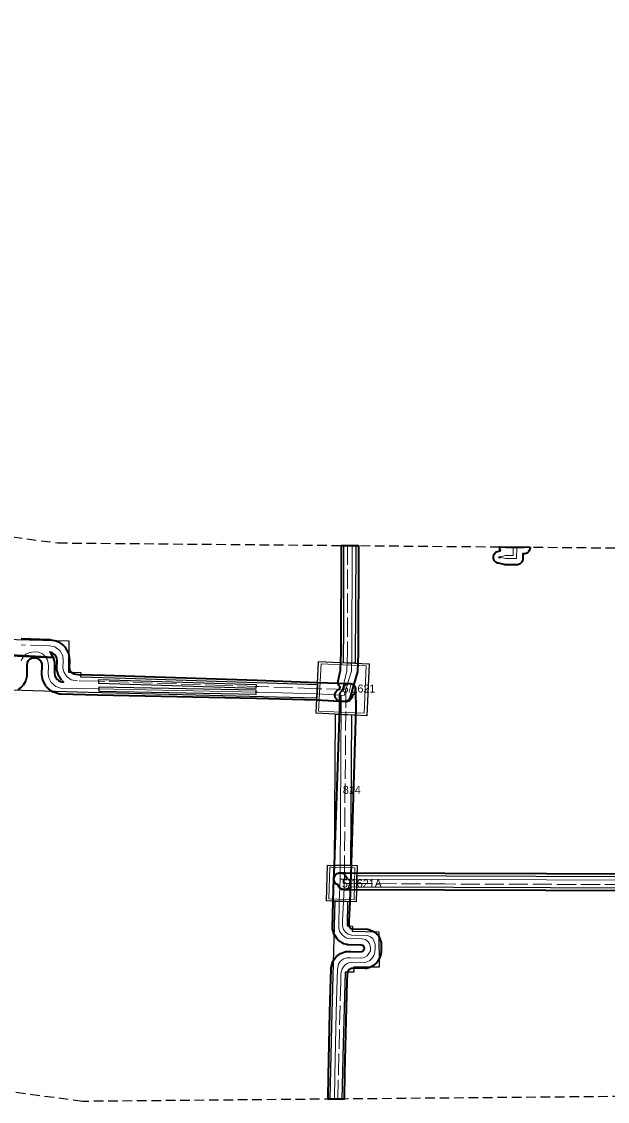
# Model space of a CAD drawing. Extents: x -451331 to -449998, y -1101254 to -1101132.
# Drawn here: x -450463.8 to -450397.9, y -1101253.5 to -1101132.1 of the extents above; entities that cross this region are included whole.
import ezdxf

# ---------------------------------------------------------------- set-up
doc = ezdxf.new("R2010")
doc.units = 0
doc.header["$LTSCALE"] = 0.36
doc.header["$PDMODE"] = 32
doc.header["$PDSIZE"] = 0.18
doc.linetypes.add('LONG_DASHED', pattern=[7.5, 6, -1.5])
doc.linetypes.add('MEDIUM_DASHED', pattern=[4.5, 3, -1.5])
for name, color, linetype, lineweight in [('2', 7, 'Continuous', 13), ('3', 7, 'Continuous', 25), ('62', 7, 'MEDIUM_DASHED', 25), ('8', 7, 'Continuous', 35)]:
    doc.layers.add(name, color=color, linetype=linetype, lineweight=lineweight)
doc.layers.add('4', color=7, linetype='Continuous')

msp = doc.modelspace()

# ---------------------------------------------------------------- linework, layer by layer
at = {"layer": '2'}
for p, q in [((-450409.321, -1101191.258), (-450409.64, -1101191.165)), ((-450427.843, -1101208.474), (-450427.84, -1101207.848)), ((-450427.95, -1101228.513), (-450427.989, -1101229.466))]:
    msp.add_line(p, q, dxfattribs=at)
at = {"layer": '2', "linetype": 'LONG_DASHED'}
for p, q in [((-450427.321, -1101208.495), (-450427.32, -1101207.206)), ((-450427.515, -1101229.486), (-450427.495, -1101229.013))]:
    msp.add_line(p, q, dxfattribs=at)
for points in [[(-450427.111, -1101191.007), (-450427.14, -1101203.013), (-450427.199, -1101205.113), (-450427.493, -1101206.369)], [(-450410.013, -1101192.327), (-450409.396, -1101192.12), (-450408.694, -1101192.129), (-450408.492, -1101192.12), (-450408.499, -1101191.175)], [(-450455.129, -1101206.277), (-450457.469, -1101206.21), (-450458.165, -1101206.097), (-450458.682, -1101205.745), (-450458.981, -1101205.301), (-450459.109, -1101204.789), (-450459.067, -1101203.978), (-450459.126, -1101203.422), (-450459.458, -1101202.817), (-450460.023, -1101202.407), (-450460.6, -1101202.279), (-450463.815, -1101202.179)], [(-450437.08, -1101206.868), (-450437.31, -1101206.859), (-450440.958, -1101206.74), (-450454.5, -1101206.295), (-450455.129, -1101206.277)], [(-450427.493, -1101206.369), (-450427.5, -1101206.398), (-450427.685, -1101207.195)], [(-450427.32, -1101207.206), (-450430.563, -1101207.105), (-450437.08, -1101206.868)], [(-450427.495, -1101229.013), (-450427.475, -1101228.025), (-450427.321, -1101209.263), (-450427.321, -1101208.495)], [(-450428.21, -1101253.252), (-450428.145, -1101250.298), (-450427.888, -1101240.012), (-450427.864, -1101239.152), (-450427.818, -1101238.86), (-450427.715, -1101238.592), (-450427.58, -1101238.376), (-450427.385, -1101238.168), (-450427.162, -1101238.01), (-450426.898, -1101237.894), (-450426.708, -1101237.847), (-450425.142, -1101237.88), (-450424.935, -1101237.831), (-450424.613, -1101237.657), (-450424.36, -1101237.42), (-450424.164, -1101237.106), (-450424.057, -1101236.742), (-450424.033, -1101236.247), (-450424.029, -1101235.836), (-450424.118, -1101235.523), (-450424.294, -1101235.208), (-450424.552, -1101235.01), (-450424.888, -1101234.865), (-450426.684, -1101234.814), (-450427.064, -1101234.693), (-450427.341, -1101234.495), (-450427.576, -1101234.182), (-450427.696, -1101233.808), (-450427.685, -1101233.225), (-450427.579, -1101231.023), (-450427.515, -1101229.486)], [(-450426.579, -1101229.016), (-450427.323, -1101229.013), (-450427.495, -1101229.013)], [(-450393.344, -1101229.141), (-450416.205, -1101229.066), (-450426.579, -1101229.016)]]:
    msp.add_lwpolyline(points, dxfattribs=at)
at = {"layer": '2'}
for points in [[(-450427.094, -1101206.466), (-450427.075, -1101206.4), (-450426.69, -1101205.134), (-450426.623, -1101203.118), (-450426.597, -1101191.011)], [(-450408.113, -1101191.179), (-450408.12, -1101192.486), (-450409.365, -1101192.475), (-450410.013, -1101192.327)], [(-450409.321, -1101191.258), (-450407.313, -1101191.258), (-450407.312, -1101191.186)], [(-450455.194, -1101207.118), (-450457.391, -1101207.074), (-450459.366, -1101207.034), (-450459.921, -1101206.849), (-450460.445, -1101206.396), (-450460.703, -1101205.888), (-450460.774, -1101205.415), (-450460.739, -1101204.626), (-450460.749, -1101204.21), (-450460.872, -1101203.817), (-450461.054, -1101203.524), (-450461.419, -1101203.197), (-450461.831, -1101203.015), (-450462.34, -1101202.969), (-450462.849, -1101203.036), (-450463.273, -1101203.243), (-450463.585, -1101203.55), (-450463.786, -1101203.928)], [(-450427.84, -1101207.848), (-450427.489, -1101207.861), (-450427.094, -1101206.466)], [(-450437.173, -1101207.506), (-450437.33, -1101207.501), (-450440.843, -1101207.426), (-450455.194, -1101207.118)], [(-450427.84, -1101207.848), (-450430.595, -1101207.703), (-450437.173, -1101207.506)], [(-450427.95, -1101228.513), (-450427.942, -1101227.997), (-450427.843, -1101208.474)], [(-450427.989, -1101229.466), (-450428.05, -1101231.01), (-450428.112, -1101234.044), (-450427.993, -1101234.43), (-450427.705, -1101234.838), (-450427.326, -1101235.108), (-450427.004, -1101235.204), (-450425.479, -1101235.241), (-450425.158, -1101235.32), (-450424.872, -1101235.501), (-450424.657, -1101235.765), (-450424.526, -1101236.16), (-450424.553, -1101236.577), (-450424.714, -1101236.89), (-450424.9, -1101237.134), (-450425.315, -1101237.357), (-450425.704, -1101237.398), (-450426.774, -1101237.362), (-450427.193, -1101237.36), (-450427.572, -1101237.493), (-450427.936, -1101237.781), (-450428.143, -1101238.098), (-450428.265, -1101238.648), (-450428.33, -1101240.954), (-450428.404, -1101243.537), (-450428.545, -1101250.606), (-450428.587, -1101253.256)], [(-450427.95, -1101228.513), (-450427.32, -1101228.513), (-450426.595, -1101228.516)], [(-450426.595, -1101228.516), (-450416.203, -1101228.566), (-450393.342, -1101228.641)]]:
    msp.add_lwpolyline(points, dxfattribs=at)
at = {"layer": '3'}
for points in [[(-450427.586, -1101204.181), (-450427.533, -1101200.035), (-450427.522, -1101191.003), (-450426.207, -1101191.015), (-450426.261, -1101204.241)], [(-450430.389, -1101204.049), (-450424.674, -1101204.319), (-450424.95, -1101210.147), (-450430.665, -1101209.877)], [(-450455.059, -1101206.081), (-450437.406, -1101206.62), (-450437.42, -1101207.068), (-450455.073, -1101206.528)], [(-450455.027, -1101206.906), (-450437.424, -1101207.248), (-450437.435, -1101207.773), (-450455.038, -1101207.432)], [(-450428.486, -1101209.98), (-450426.685, -1101210.065), (-450426.803, -1101226.978), (-450428.598, -1101226.947)], [(-450426.141, -1101231.063), (-450429.488, -1101230.97), (-450429.375, -1101226.934), (-450426.049, -1101226.991)], [(-450428.507, -1101230.997), (-450427.131, -1101231.036), (-450427.158, -1101233.762), (-450426.576, -1101233.795), (-450426.583, -1101234.366), (-450423.586, -1101234.43), (-450423.566, -1101238.432), (-450426.442, -1101238.437), (-450426.421, -1101238.977), (-450427.377, -1101238.966), (-450427.614, -1101247.044), (-450427.757, -1101253.248), (-450429.083, -1101253.26), (-450428.882, -1101244.969), (-450428.527, -1101230.997)]]:
    msp.add_lwpolyline(points, close=True, dxfattribs=at)
for points in [[(-450465.786, -1101201.536), (-450458.428, -1101201.743), (-450458.465, -1101205.262), (-450457.108, -1101205.299), (-450457.121, -1101205.769), (-450452.083, -1101205.924), (-450430.512, -1101206.65), (-450430.584, -1101208.162), (-450456.247, -1101207.547), (-450467.469, -1101207.201)], [(-450329.864, -1101232.315), (-450333.399, -1101232.315), (-450333.397, -1101230.456), (-450333.898, -1101230.453), (-450333.898, -1101229.798), (-450359.843, -1101229.58), (-450388.544, -1101229.543), (-450388.534, -1101230.025), (-450389.144, -1101230.033), (-450389.169, -1101232.065), (-450392.677, -1101232.065), (-450392.736, -1101230.012), (-450393.421, -1101230.011), (-450393.431, -1101229.541), (-450426.085, -1101229.419), (-450426.062, -1101228.119), (-450395.865, -1101228.233), (-450345.044, -1101228.383), (-450323.284, -1101228.506)]]:
    msp.add_lwpolyline(points, dxfattribs=at)
at = {"layer": '3', "lineweight": 13}
for points in [[(-450429.341, -1101204.364), (-450425.019, -1101204.553), (-450425.25, -1101209.863), (-450430.369, -1101209.617), (-450430.075, -1101204.33)], [(-450428.924, -1101227.192), (-450426.312, -1101227.238), (-450426.385, -1101230.836), (-450429.236, -1101230.75), (-450429.097, -1101227.192)]]:
    msp.add_lwpolyline(points, close=True, dxfattribs=at)
at = {"layer": '4'}
msp.add_point((-450410.013, -1101192.327), dxfattribs=at)
at = {"layer": '62'}
msp.add_lwpolyline([(-450786.261, -1101210.25), (-451322.174, -1101190.711), (-451330.547, -1101132.096), (-450766.722, -1101150.239), (-450459.689, -1101190.711), (-449997.743, -1101194.898), (-449997.743, -1101249.327), (-450456.897, -1101253.514)], close=True, dxfattribs=at)
at = {"layer": '8'}
for points in [[(-450425.897, -1101191.018), (-450425.923, -1101203.12), (-450425.924, -1101203.142), (-450425.991, -1101205.157), (-450426, -1101205.248), (-450426.021, -1101205.337), (-450426.403, -1101206.597), (-450426.815, -1101208.052), (-450426.856, -1101208.16), (-450426.915, -1101208.261), (-450426.989, -1101208.35), (-450427.077, -1101208.427), (-450427.176, -1101208.487), (-450427.284, -1101208.53), (-450427.398, -1101208.555), (-450427.514, -1101208.56), (-450427.864, -1101208.548), (-450427.98, -1101208.534), (-450428.093, -1101208.501), (-450428.198, -1101208.45), (-450428.293, -1101208.382), (-450428.375, -1101208.299), (-450428.443, -1101208.204), (-450428.494, -1101208.098), (-450428.526, -1101207.986), (-450428.539, -1101207.87), (-450428.533, -1101207.753), (-450428.508, -1101207.639), (-450428.463, -1101207.531), (-450428.402, -1101207.432), (-450428.325, -1101207.344), (-450428.234, -1101207.27), (-450428.132, -1101207.213), (-450428.022, -1101207.173), (-450427.947, -1101206.91), (-450428.026, -1101206.832), (-450428.091, -1101206.743), (-450428.141, -1101206.644), (-450428.175, -1101206.539), (-450428.193, -1101206.429), (-450428.192, -1101206.319), (-450428.174, -1101206.209), (-450427.896, -1101205.022), (-450427.84, -1101203.003), (-450427.811, -1101191)], [(-450406.612, -1101191.192), (-450406.612, -1101191.26), (-450406.623, -1101191.381), (-450406.655, -1101191.499), (-450406.707, -1101191.609), (-450406.777, -1101191.708), (-450406.863, -1101191.794), (-450406.963, -1101191.864), (-450407.074, -1101191.916), (-450407.191, -1101191.947), (-450407.313, -1101191.958), (-450407.417, -1101191.958), (-450407.42, -1101192.49), (-450407.43, -1101192.599), (-450407.456, -1101192.706), (-450407.499, -1101192.807), (-450407.557, -1101192.901), (-450407.629, -1101192.984), (-450407.713, -1101193.055), (-450407.807, -1101193.112), (-450407.909, -1101193.153), (-450408.017, -1101193.178), (-450408.126, -1101193.186), (-450409.37, -1101193.175), (-450409.446, -1101193.17), (-450409.521, -1101193.157), (-450410.161, -1101193.011), (-450410.169, -1101193.009), (-450410.174, -1101193.008), (-450410.278, -1101192.976), (-450410.375, -1101192.927), (-450410.473, -1101192.858), (-450410.557, -1101192.773), (-450410.626, -1101192.675), (-450410.677, -1101192.567), (-450410.709, -1101192.452), (-450410.72, -1101192.333), (-450410.712, -1101192.213), (-450410.683, -1101192.097), (-450410.634, -1101191.988), (-450410.568, -1101191.888), (-450410.486, -1101191.802), (-450410.39, -1101191.73), (-450410.283, -1101191.676), (-450410.169, -1101191.641), (-450409.949, -1101191.567), (-450409.988, -1101191.47), (-450410.013, -1101191.368), (-450410.021, -1101191.264), (-450410.015, -1101191.162)]]:
    msp.add_lwpolyline(points, close=True, dxfattribs=at)
for points in [[(-450459.262, -1101206.137), (-450459.563, -1101205.69), (-450459.621, -1101205.585), (-450459.66, -1101205.471), (-450459.788, -1101204.96), (-450459.806, -1101204.857), (-450459.809, -1101204.753), (-450459.769, -1101203.997), (-450459.807, -1101203.635), (-450459.996, -1101203.291), (-450460.316, -1101203.059), (-450460.593, -1101202.998), (-450460.587, -1101203.004), (-450460.518, -1101203.074), (-450460.461, -1101203.154), (-450460.278, -1101203.446), (-450460.236, -1101203.524), (-450460.204, -1101203.607), (-450549.017, -1101198.677)], [(-450505.347, -1101201.513), (-450460.204, -1101203.607), (-450460.081, -1101204), (-450460.059, -1101204.095), (-450460.049, -1101204.193), (-450460.039, -1101204.609), (-450460.039, -1101204.626), (-450460.04, -1101204.657), (-450460.072, -1101205.378), (-450460.027, -1101205.672), (-450459.883, -1101205.956), (-450459.568, -1101206.229), (-450459.245, -1101206.337), (-450459.051, -1101206.341), (-450459.075, -1101206.324), (-450459.145, -1101206.27), (-450459.208, -1101206.207)], [(-450463.793, -1101201.479), (-450460.579, -1101201.58), (-450460.513, -1101201.585), (-450460.449, -1101201.596), (-450459.872, -1101201.724), (-450459.78, -1101201.751), (-450459.693, -1101201.79), (-450459.612, -1101201.84), (-450459.047, -1101202.25), (-450458.968, -1101202.317), (-450458.9, -1101202.394), (-450458.844, -1101202.48), (-450458.512, -1101203.085), (-450458.473, -1101203.169), (-450458.446, -1101203.257), (-450458.43, -1101203.348), (-450458.371, -1101203.904), (-450458.367, -1101203.978), (-450458.368, -1101204.014), (-450458.405, -1101204.721), (-450458.332, -1101205.012), (-450458.177, -1101205.242), (-450457.899, -1101205.431), (-450457.403, -1101205.511), (-450454.479, -1101205.595), (-450437.285, -1101206.16), (-450430.539, -1101206.405), (-450426.887, -1101206.52), (-450426.77, -1101206.533), (-450426.658, -1101206.565), (-450426.553, -1101206.616), (-450426.457, -1101206.684), (-450426.374, -1101206.766), (-450426.306, -1101206.861), (-450426.255, -1101206.966), (-450426.222, -1101207.078), (-450426.208, -1101207.194), (-450426.214, -1101207.311)], [(-450426.239, -1101207.425), (-450426.282, -1101207.534), (-450426.343, -1101207.633), (-450426.42, -1101207.722), (-450426.51, -1101207.796), (-450426.612, -1101207.854), (-450426.618, -1101207.969), (-450426.642, -1101208.081), (-450426.685, -1101208.188), (-450426.745, -1101208.287), (-450426.82, -1101208.374), (-450426.908, -1101208.448), (-450427.007, -1101208.506), (-450427.115, -1101208.548), (-450427.227, -1101208.571), (-450427.342, -1101208.576), (-450430.624, -1101208.402), (-450437.348, -1101208.201), (-450455.208, -1101207.818), (-450459.382, -1101207.734), (-450459.486, -1101207.724), (-450459.587, -1101207.699), (-450460.142, -1101207.513), (-450460.227, -1101207.479), (-450460.306, -1101207.434), (-450460.379, -1101207.378), (-450460.903, -1101206.925), (-450460.967, -1101206.862), (-450461.023, -1101206.791), (-450461.069, -1101206.713), (-450461.327, -1101206.206), (-450461.369, -1101206.102), (-450461.395, -1101205.993), (-450461.466, -1101205.52), (-450461.473, -1101205.453), (-450461.473, -1101205.385), (-450461.44, -1101204.619), (-450461.447, -1101204.325), (-450461.514, -1101204.111), (-450461.596, -1101203.979), (-450461.804, -1101203.792), (-450462.009, -1101203.702), (-450462.326, -1101203.673), (-450462.644, -1101203.715), (-450462.864, -1101203.823), (-450463.018, -1101203.974), (-450463.114, -1101204.155), (-450463.165, -1101204.469), (-450463.157, -1101204.921), (-450463.157, -1101204.929), (-450463.152, -1101205.533), (-450463.157, -1101205.62), (-450463.173, -1101205.706), (-450463.28, -1101206.135), (-450463.314, -1101206.235), (-450463.362, -1101206.329), (-450463.591, -1101206.704), (-450463.662, -1101206.801), (-450463.748, -1101206.884), (-450464.183, -1101207.235)], [(-450427.439, -1101229.711), (-450427.549, -1101229.711), (-450427.658, -1101229.694), (-450427.763, -1101229.66), (-450427.861, -1101229.61), (-450427.95, -1101229.545), (-450428.028, -1101229.467), (-450428.092, -1101229.378), (-450428.142, -1101229.28), (-450428.176, -1101229.175), (-450428.279, -1101229.131), (-450428.373, -1101229.07), (-450428.457, -1101228.996), (-450428.528, -1101228.909), (-450428.583, -1101228.811), (-450428.623, -1101228.707), (-450428.645, -1101228.597), (-450428.65, -1101228.485), (-450428.629, -1101227.972), (-450427.996, -1101209.287), (-450427.995, -1101209.258), (-450428.005, -1101207.882), (-450428.004, -1101207.831), (-450428, -1101207.785), (-450427.992, -1101207.74), (-450427.982, -1101207.695), (-450427.968, -1101207.651), (-450427.952, -1101207.609), (-450427.933, -1101207.567), (-450427.912, -1101207.526), (-450427.887, -1101207.488), (-450427.861, -1101207.45), (-450427.832, -1101207.415), (-450427.8, -1101207.381), (-450427.767, -1101207.35), (-450427.732, -1101207.321), (-450427.694, -1101207.295), (-450427.656, -1101207.27), (-450427.615, -1101207.249), (-450427.608, -1101207.246), (-450427.608, -1101207.219), (-450427.607, -1101207.173), (-450427.603, -1101207.128), (-450427.595, -1101207.083), (-450427.585, -1101207.038), (-450427.571, -1101206.994), (-450427.555, -1101206.951), (-450427.536, -1101206.91), (-450427.515, -1101206.869), (-450427.49, -1101206.83), (-450427.464, -1101206.793), (-450427.435, -1101206.758), (-450427.403, -1101206.724), (-450427.37, -1101206.693), (-450427.335, -1101206.664), (-450427.297, -1101206.637), (-450427.259, -1101206.613), (-450427.218, -1101206.592), (-450427.176, -1101206.573), (-450427.134, -1101206.556), (-450427.09, -1101206.543), (-450427.045, -1101206.533), (-450427, -1101206.525), (-450426.954, -1101206.521), (-450426.909, -1101206.519), (-450426.863, -1101206.521), (-450426.817, -1101206.525), (-450426.772, -1101206.533), (-450426.727, -1101206.543), (-450426.684, -1101206.556), (-450426.641, -1101206.573), (-450426.599, -1101206.592), (-450426.559, -1101206.613), (-450426.52, -1101206.637), (-450426.482, -1101206.664), (-450426.447, -1101206.693), (-450426.413, -1101206.724), (-450426.382, -1101206.758), (-450426.353, -1101206.793), (-450426.326, -1101206.83), (-450426.302, -1101206.869), (-450426.281, -1101206.91), (-450426.262, -1101206.951), (-450426.246, -1101206.994), (-450426.232, -1101207.038), (-450426.222, -1101207.083), (-450426.215, -1101207.128), (-450426.21, -1101207.173), (-450426.208, -1101207.219), (-450426.208, -1101207.502), (-450426.196, -1101209.238), (-450426.196, -1101209.243), (-450426.196, -1101209.264), (-450426.197, -1101209.289), (-450426.754, -1101228.045), (-450426.754, -1101228.053), (-450426.796, -1101229.043), (-450426.809, -1101229.154), (-450426.841, -1101229.262), (-450426.889, -1101229.364)], [(-450423.334, -1101236.281), (-450423.358, -1101236.776), (-450423.367, -1101236.859), (-450423.385, -1101236.94), (-450423.493, -1101237.304), (-450423.526, -1101237.392), (-450423.57, -1101237.476), (-450423.766, -1101237.79), (-450423.819, -1101237.864), (-450423.881, -1101237.93), (-450424.134, -1101238.167), (-450424.203, -1101238.225), (-450424.28, -1101238.273), (-450424.602, -1101238.447), (-450424.686, -1101238.486), (-450424.774, -1101238.513), (-450424.98, -1101238.561), (-450425.068, -1101238.576), (-450425.157, -1101238.58), (-450426.63, -1101238.548), (-450426.671, -1101238.559), (-450426.815, -1101238.622), (-450426.922, -1101238.698), (-450427.023, -1101238.806), (-450427.086, -1101238.906), (-450427.138, -1101239.042), (-450427.166, -1101239.217), (-450427.189, -1101240.03), (-450427.445, -1101250.315), (-450427.51, -1101253.246), (-450429.287, -1101253.262), (-450429.245, -1101250.594), (-450429.104, -1101243.523), (-450429.103, -1101243.517), (-450429.03, -1101240.934), (-450428.964, -1101238.628), (-450428.959, -1101238.563), (-450428.948, -1101238.497), (-450428.827, -1101237.948), (-450428.804, -1101237.867), (-450428.771, -1101237.789), (-450428.73, -1101237.716), (-450428.521, -1101237.396), (-450428.453, -1101237.308), (-450428.371, -1101237.232), (-450428.006, -1101236.943), (-450427.91, -1101236.879), (-450427.804, -1101236.832), (-450427.425, -1101236.699), (-450427.309, -1101236.669), (-450427.19, -1101236.66), (-450426.771, -1101236.662), (-450426.75, -1101236.662), (-450425.728, -1101236.697), (-450425.525, -1101236.675), (-450425.365, -1101236.589), (-450425.308, -1101236.515), (-450425.242, -1101236.386), (-450425.233, -1101236.251), (-450425.281, -1101236.108), (-450425.343, -1101236.032), (-450425.437, -1101235.972), (-450425.573, -1101235.938), (-450427.021, -1101235.904), (-450427.113, -1101235.896), (-450427.203, -1101235.875), (-450427.526, -1101235.779), (-450427.634, -1101235.737), (-450427.733, -1101235.678), (-450428.111, -1101235.408), (-450428.201, -1101235.332), (-450428.277, -1101235.242), (-450428.564, -1101234.834), (-450428.621, -1101234.739), (-450428.661, -1101234.637), (-450428.781, -1101234.251), (-450428.805, -1101234.142), (-450428.812, -1101234.03), (-450428.75, -1101230.996), (-450428.75, -1101230.982), (-450428.65, -1101228.485), (-450428.636, -1101228.367), (-450428.603, -1101228.252), (-450428.551, -1101228.146), (-450428.481, -1101228.049), (-450428.397, -1101227.966), (-450428.299, -1101227.898), (-450428.191, -1101227.848), (-450428.076, -1101227.816), (-450427.958, -1101227.805), (-450427.839, -1101227.813), (-450427.724, -1101227.842), (-450427.615, -1101227.89), (-450427.516, -1101227.956), (-450427.429, -1101228.037), (-450427.358, -1101228.132), (-450427.303, -1101228.238), (-450427.267, -1101228.351), (-450427.164, -1101228.396), (-450427.07, -1101228.457)], [(-450393.453, -1101229.84), (-450416.208, -1101229.766), (-450427.324, -1101229.713), (-450427.493, -1101229.713), (-450427.61, -1101229.704), (-450427.723, -1101229.675), (-450427.83, -1101229.628), (-450427.928, -1101229.563), (-450428.014, -1101229.483), (-450428.085, -1101229.39), (-450428.139, -1101229.287), (-450428.176, -1101229.175), (-450428.282, -1101229.129), (-450428.379, -1101229.066), (-450428.465, -1101228.988), (-450428.536, -1101228.897), (-450428.591, -1101228.795), (-450428.629, -1101228.686), (-450428.648, -1101228.572), (-450428.648, -1101228.456), (-450428.629, -1101228.342), (-450428.592, -1101228.232), (-450428.537, -1101228.13), (-450428.466, -1101228.039), (-450428.381, -1101227.96), (-450428.284, -1101227.897), (-450428.178, -1101227.851), (-450428.066, -1101227.822), (-450427.95, -1101227.813), (-450427.319, -1101227.813), (-450416.2, -1101227.866), (-450393.34, -1101227.941)], [(-450426.953, -1101229.457), (-450427.031, -1101229.538), (-450427.121, -1101229.605), (-450427.221, -1101229.657), (-450427.328, -1101229.693), (-450427.439, -1101229.711)], [(-450426.987, -1101228.532), (-450426.917, -1101228.619), (-450426.861, -1101228.716), (-450426.822, -1101228.821), (-450426.8, -1101228.931), (-450426.796, -1101229.042), (-450426.88, -1101231.055), (-450426.985, -1101233.249), (-450426.994, -1101233.705), (-450426.945, -1101233.856), (-450426.846, -1101233.988), (-450426.747, -1101234.059), (-450426.565, -1101234.117), (-450424.869, -1101234.165), (-450424.782, -1101234.173), (-450424.696, -1101234.192), (-450424.614, -1101234.221), (-450424.275, -1101234.367), (-450424.198, -1101234.406), (-450424.126, -1101234.454), (-450423.868, -1101234.653), (-450423.796, -1101234.715), (-450423.734, -1101234.787), (-450423.682, -1101234.867), (-450423.507, -1101235.183), (-450423.472, -1101235.255), (-450423.445, -1101235.331), (-450423.356, -1101235.643), (-450423.335, -1101235.742), (-450423.329, -1101235.843), (-450423.333, -1101236.255), (-450423.334, -1101236.281)]]:
    msp.add_lwpolyline(points, dxfattribs=at)

# ---------------------------------------------------------------- texts
at = {"layer": '3'}
for s, p in [('5/1621 ', (-450427.677, -1101207.546)), ('814 ', (-450427.644, -1101218.936)), ('5/1621A', (-450427.755, -1101229.459))]:
    msp.add_text(s, height=0.9, dxfattribs=at).set_placement(p)

doc.saveas('drawing.dxf')
